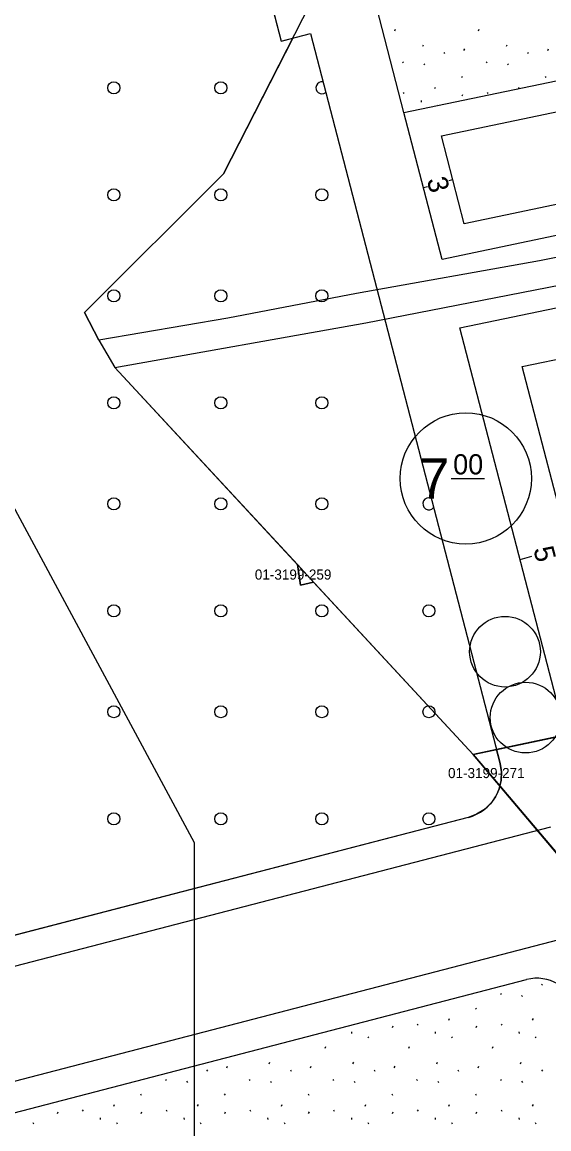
# Model space of a CAD drawing. Extents: x 419396 to 421519, y 4453567 to 4456767.
# Drawn here: x 420734.2 to 420786.3, y 4454716.9 to 4454826.5 of the extents above; entities that cross this region are included whole.
import ezdxf

# ---------------------------------------------------------------- set-up
doc = ezdxf.new("R2010")
doc.units = 0
for name, color, linetype in [('0_KADASTRO', 7, 'Continuous'), ('Level 20', 7, 'Continuous'), ('Level 21', 7, 'Continuous'), ('Level 28', 7, 'Continuous'), ('Level 29', 7, 'Continuous'), ('Level 41', 7, 'Continuous'), ('Level 47', 7, 'Continuous'), ('Level 55', 7, 'Continuous'), ('Level 58', 7, 'Continuous'), ('Level 59', 7, 'Continuous'), ('Level 62', 7, 'Continuous')]:
    doc.layers.add(name, color=color, linetype=linetype)

msp = doc.modelspace()

# ---------------------------------------------------------------- linework, layer by layer
at = {"layer": '0_KADASTRO'}
for p, q in [((420781.52, 4454753.08), (420781.16, 4454754.45)), ((420781.65, 4454752.23), (420781.52, 4454753.08)), ((420781.62, 4454751.37), (420781.65, 4454752.23)), ((420781.49, 4454750.85), (420801.19, 4454727.51))]:
    msp.add_line(p, q, dxfattribs=at)
for points in [[(420740.35, 4454797.74), (420754.14, 4454811.48), (420767.48, 4454837.67), (420871.83, 4454868.52), (420870.03, 4454820.5), (420854.85, 4454816.89), (420839.6, 4454813.65), (420821.55, 4454809.98), (420803.55, 4454806.49), (420785.42, 4454802.86), (420767.3, 4454799.62), (420754.56, 4454797.18), (420741.78, 4454795.01)], [(420743.37, 4454792.29), (420768.22, 4454796.71), (420804.28, 4454803.73), (420840.45, 4454811.21), (420870.47, 4454818.21), (420881.55, 4454819.08), (420870.74, 4454802.46), (420866.67, 4454800.1), (420859.62, 4454792.07), (420851.07, 4454785.89), (420839.81, 4454766.75), (420778.86, 4454753.97)], [(420761.45, 4454772.76), (420763.05, 4454771.04), (420761.76, 4454770.74)], [(420778.86, 4454753.97), (420839.81, 4454766.75), (420832.46, 4454758.38), (420815.3, 4454738.85), (420809.5, 4454727.6), (420805.81, 4454724.14), (420801.19, 4454727.51)]]:
    msp.add_lwpolyline(points, close=True, dxfattribs=at)
for points in [[(420755.35, 4454841.87), (420759.83, 4454824.62), (420760.99, 4454824.92), (420754.14, 4454811.48), (420740.35, 4454797.74), (420741.78, 4454795.01), (420743.37, 4454792.29), (420761.45, 4454772.76), (420761.76, 4454770.74), (420763.05, 4454771.04), (420778.86, 4454753.97), (420781.49, 4454750.85), (420781.42, 4454750.54), (420781.05, 4454749.75), (420780.55, 4454749.06), (420779.91, 4454748.48), (420779.18, 4454748.03), (420778.37, 4454747.73), (420695.05, 4454726.08)], [(420788.02, 4454755.89), (420781.16, 4454754.45), (420781.52, 4454753.08), (420781.65, 4454752.23)], [(420781.16, 4454754.45), (420778.86, 4454753.97), (420781.49, 4454750.85), (420781.62, 4454751.37)], [(420781.65, 4454752.23), (420781.62, 4454751.37), (420781.49, 4454750.85)]]:
    msp.add_lwpolyline(points, dxfattribs=at)
at = {"layer": 'Level 20'}
for p, q in [((420775.7, 4454815.24), (420857.13, 4454832.3)), ((420857.13, 4454823.11), (420777.97, 4454806.51)), ((420777.97, 4454806.51), (420775.7, 4454815.24)), ((420776.83, 4454810.88), (420776.45, 4454810.78)), ((420783.7, 4454792.39), (420875.81, 4454811.7)), ((420773.93, 4454810.12), (420774.32, 4454810.22)), ((420792.98, 4454756.69), (420783.7, 4454792.39)), ((420783.5, 4454773.28), (420784.66, 4454773.59))]:
    msp.add_line(p, q, dxfattribs=at)
at = {"layer": 'Level 21'}
for p, q in [((420732.07, 4454780.84), (420751.24, 4454745.23)), ((420732.07, 4454780.84), (420751.24, 4454745.23)), ((420751.24, 4454745.23), (420751.24, 4454707.42)), ((420751.24, 4454745.23), (420751.24, 4454733.61))]:
    msp.add_line(p, q, dxfattribs=at)
at = {"layer": 'Level 28'}
for p, q in [((420755.35, 4454841.87), (420759.83, 4454824.62)), ((420772, 4454817.53), (420767.98, 4454833)), ((420759.83, 4454824.62), (420762.73, 4454825.37)), ((420762.73, 4454825.37), (420781.52, 4454753.08)), ((420775.78, 4454802.99), (420772, 4454817.53)), ((420788.14, 4454755.43), (420777.54, 4454796.21)), ((420778.37, 4454747.73), (420731.59, 4454735.57)), ((420731.41, 4454717.96), (420784.13, 4454731.66))]:
    msp.add_line(p, q, dxfattribs=at)
for centre, radius, start, end in [((420777.27, 4454751.98), 4.39, 284.5669, 14.5669), ((420785.16, 4454727.72), 4.07, 14.5669, 104.5669)]:
    msp.add_arc(centre, radius, start, end, dxfattribs=at)
at = {"layer": 'Level 29'}
for p, q in [((420868.7, 4454822.46), (420775.78, 4454802.99)), ((420777.54, 4454796.21), (420879.38, 4454817.55))]:
    msp.add_line(p, q, dxfattribs=at)
at = {"layer": 'Level 41'}
for p, q in [((420771.08, 4454825.63), (420771.15, 4454825.79)), ((420779.37, 4454825.63), (420779.44, 4454825.79)), ((420773.85, 4454824.1), (420773.92, 4454824.26)), ((420782.14, 4454824.1), (420782.21, 4454824.26)), ((420775.95, 4454823.49), (420776.02, 4454823.38)), ((420777.93, 4454823.69), (420778.01, 4454823.85)), ((420784.24, 4454823.49), (420784.31, 4454823.38)), ((420786.23, 4454823.69), (420786.3, 4454823.85)), ((420771.86, 4454822.56), (420771.93, 4454822.45)), ((420773.96, 4454822.37), (420774.03, 4454822.26)), ((420780.15, 4454822.56), (420780.23, 4454822.45)), ((420782.25, 4454822.37), (420782.32, 4454822.26)), ((420777.7, 4454821.1), (420777.77, 4454821)), ((420785.99, 4454821.1), (420786.06, 4454821)), ((420775.06, 4454819.91), (420775.13, 4454820.07)), ((420783.35, 4454819.91), (420783.42, 4454820.07)), ((420771.93, 4454819.53), (420772, 4454819.42)), ((420773.69, 4454818.74), (420773.7, 4454818.58)), ((420777.76, 4454819.18), (420777.83, 4454819.34)), ((420780.22, 4454819.53), (420780.29, 4454819.42)), ((420775.32, 4454818.27), (420775.34, 4454818.23)), ((420785.63, 4454731.22), (420785.7, 4454731.11)), ((420781.55, 4454730.29), (420781.62, 4454730.18)), ((420783.65, 4454730.1), (420783.72, 4454729.99)), ((420779.09, 4454728.84), (420779.16, 4454728.73)), ((420776.45, 4454727.65), (420776.52, 4454727.8)), ((420784.74, 4454727.65), (420784.81, 4454727.8)), ((420766.79, 4454726.47), (420766.8, 4454726.31)), ((420770.86, 4454726.92), (420770.93, 4454727.08)), ((420773.32, 4454727.26), (420773.39, 4454727.15)), ((420775.08, 4454726.47), (420775.1, 4454726.31)), ((420779.15, 4454726.92), (420779.22, 4454727.08)), ((420781.61, 4454727.26), (420781.69, 4454727.15)), ((420783.37, 4454726.47), (420783.39, 4454726.31)), ((420768.42, 4454726), (420768.49, 4454725.89)), ((420776.71, 4454726), (420776.78, 4454725.89)), ((420785, 4454726), (420785.07, 4454725.89)), ((420764.18, 4454724.86), (420764.25, 4454725.02)), ((420772.47, 4454724.86), (420772.54, 4454725.02)), ((420780.77, 4454724.86), (420780.84, 4454725.02)), ((420758.66, 4454723.33), (420758.73, 4454723.49)), ((420766.95, 4454723.33), (420767.02, 4454723.49)), ((420775.24, 4454723.33), (420775.31, 4454723.49)), ((420783.54, 4454723.33), (420783.61, 4454723.49)), ((420752.46, 4454722.71), (420752.53, 4454722.6)), ((420754.45, 4454722.92), (420754.52, 4454723.08)), ((420760.75, 4454722.71), (420760.82, 4454722.6)), ((420762.74, 4454722.92), (420762.81, 4454723.08)), ((420769.05, 4454722.71), (420769.12, 4454722.6)), ((420771.03, 4454722.92), (420771.11, 4454723.08)), ((420777.34, 4454722.71), (420777.41, 4454722.6)), ((420779.33, 4454722.92), (420779.4, 4454723.08)), ((420785.63, 4454722.71), (420785.7, 4454722.6)), ((420748.38, 4454721.78), (420748.45, 4454721.67)), ((420750.47, 4454721.59), (420750.55, 4454721.48)), ((420756.67, 4454721.78), (420756.74, 4454721.67)), ((420758.77, 4454721.59), (420758.84, 4454721.48)), ((420764.96, 4454721.78), (420765.03, 4454721.67)), ((420767.06, 4454721.59), (420767.13, 4454721.48)), ((420773.25, 4454721.78), (420773.33, 4454721.67)), ((420775.35, 4454721.59), (420775.42, 4454721.48)), ((420781.55, 4454721.78), (420781.62, 4454721.67)), ((420783.65, 4454721.59), (420783.72, 4454721.48)), ((420745.92, 4454720.33), (420745.99, 4454720.22)), ((420754.21, 4454720.33), (420754.28, 4454720.22)), ((420762.51, 4454720.33), (420762.58, 4454720.22)), ((420770.8, 4454720.33), (420770.87, 4454720.22)), ((420779.09, 4454720.33), (420779.16, 4454720.22)), ((420740.15, 4454718.75), (420740.22, 4454718.64)), ((420743.28, 4454719.14), (420743.35, 4454719.29)), ((420748.44, 4454718.75), (420748.51, 4454718.64)), ((420751.57, 4454719.14), (420751.64, 4454719.29)), ((420756.74, 4454718.75), (420756.81, 4454718.64)), ((420759.86, 4454719.14), (420759.94, 4454719.29)), ((420765.03, 4454718.75), (420765.1, 4454718.64)), ((420768.16, 4454719.14), (420768.23, 4454719.29)), ((420773.32, 4454718.75), (420773.39, 4454718.64)), ((420776.45, 4454719.14), (420776.52, 4454719.29)), ((420781.61, 4454718.75), (420781.69, 4454718.64)), ((420784.74, 4454719.14), (420784.81, 4454719.29)), ((420737.68, 4454718.41), (420737.76, 4454718.57)), ((420741.91, 4454717.96), (420741.93, 4454717.8)), ((420745.98, 4454718.41), (420746.05, 4454718.57)), ((420750.2, 4454717.96), (420750.22, 4454717.8)), ((420754.27, 4454718.41), (420754.34, 4454718.57)), ((420758.49, 4454717.96), (420758.51, 4454717.8)), ((420762.56, 4454718.41), (420762.64, 4454718.57)), ((420766.79, 4454717.96), (420766.8, 4454717.8)), ((420770.86, 4454718.41), (420770.93, 4454718.57)), ((420775.08, 4454717.96), (420775.1, 4454717.8)), ((420779.15, 4454718.41), (420779.22, 4454718.57)), ((420783.37, 4454717.96), (420783.39, 4454717.8)), ((420735.24, 4454717.49), (420735.31, 4454717.38)), ((420743.54, 4454717.49), (420743.61, 4454717.38)), ((420751.83, 4454717.49), (420751.9, 4454717.38)), ((420760.12, 4454717.49), (420760.19, 4454717.38)), ((420768.42, 4454717.49), (420768.49, 4454717.38)), ((420776.71, 4454717.49), (420776.78, 4454717.38)), ((420785, 4454717.49), (420785.07, 4454717.38))]:
    msp.add_line(p, q, dxfattribs=at)
at = {"layer": 'Level 47'}
for centre in [(420743.27, 4454819.99), (420753.87, 4454819.99), (420743.27, 4454809.39), (420753.87, 4454809.39), (420763.87, 4454809.39), (420743.27, 4454799.39), (420753.87, 4454799.39), (420763.87, 4454799.39), (420743.27, 4454788.79), (420753.87, 4454788.79), (420763.87, 4454788.79), (420743.27, 4454778.79), (420753.87, 4454778.79), (420763.87, 4454778.79), (420743.27, 4454768.19), (420753.87, 4454768.19), (420763.87, 4454768.19), (420774.47, 4454768.19), (420743.27, 4454758.19), (420753.87, 4454758.19), (420763.87, 4454758.19), (420774.47, 4454758.19), (420743.27, 4454747.59), (420753.87, 4454747.59), (420763.87, 4454747.59), (420774.47, 4454747.59)]:
    msp.add_circle(centre, 0.6, dxfattribs=at)
for centre, start, end in [((420763.87, 4454819.99), 79.7852, 309.3478), ((420774.47, 4454778.79), 68.3909, 320.7421)]:
    msp.add_arc(centre, 0.6, start, end, dxfattribs=at)
at = {"layer": 'Level 55'}
for centre in [(420782, 4454764.14), (420784.04, 4454757.61)]:
    msp.add_circle(centre, 3.5, dxfattribs=at)
at = {"layer": 'Level 58'}
msp.add_line((420776.67, 4454781.3), (420779.97, 4454781.3), dxfattribs=at)
msp.add_circle((420778.12, 4454781.3), 6.5, dxfattribs=at)
at = {"layer": 'Level 59'}
msp.add_line((420772, 4454817.53), (420864.71, 4454836.95), dxfattribs=at)
at = {"layer": 'Level 62'}
for p, q in [((420786.52, 4454746.75), (420731.56, 4454732.47)), ((420787.32, 4454735.59), (420731.44, 4454721.07))]:
    msp.add_line(p, q, dxfattribs=at)

# ---------------------------------------------------------------- texts
at = {"layer": '0_KADASTRO'}
for s, p in [('01-3199-259', (420757.23, 4454771.28)), ('01-3199-271', (420776.36, 4454751.62))]:
    msp.add_text(s, height=1, dxfattribs=at).set_placement(p)
at = {"layer": 'Level 20'}
for s, p in [('3', (420774.24, 4454810.89)), ('5', (420784.79, 4454774.31))]:
    msp.add_text(s, height=2, rotation=284.5669, dxfattribs=at).set_placement(p)
at = {"layer": 'Level 58'}
for s, height, p in [('00', 1.998, (420776.87, 4454781.7)), ('7', 4, (420773.52, 4454779.3))]:
    msp.add_text(s, height=height, dxfattribs=at).set_placement(p)

doc.saveas('drawing.dxf')
